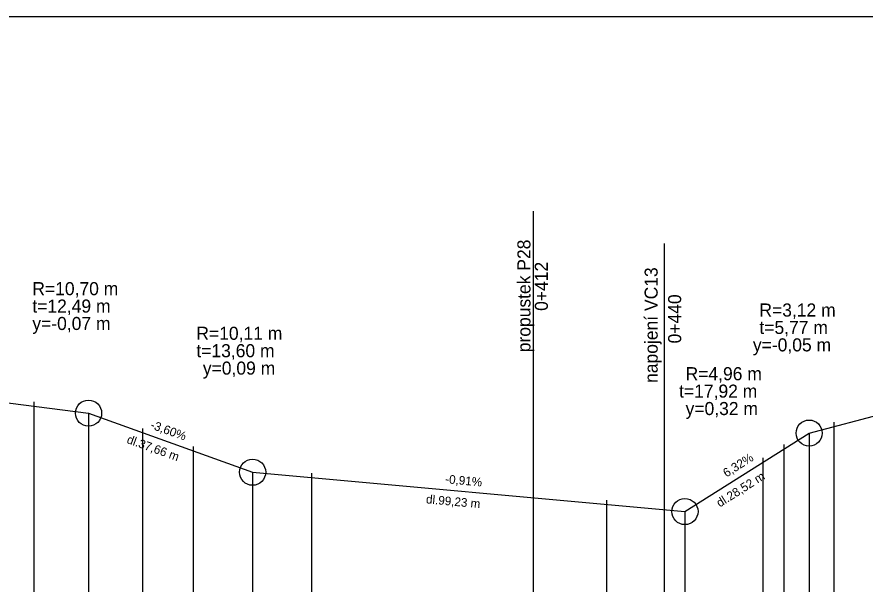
# Model space of a CAD drawing. Extents: x -632716 to -629545, y -1094726 to -1088285.
# Drawn here: x -632192 to -631997.4, y -1090800.4 to -1090670.2 of the extents above; entities that cross this region are included whole.
import ezdxf

# ---------------------------------------------------------------- set-up
doc = ezdxf.new("R2010")
doc.units = 0
for name, color, linetype in [('formát', 7, 'Continuous'), ('SKLONY_NIVELETA', 7, 'Continuous'), ('SKLONY_POPIS', 7, 'Continuous'), ('TECNY_NIVELETA', 7, 'Continuous')]:
    doc.layers.add(name, color=color, linetype=linetype)

msp = doc.modelspace()

# ---------------------------------------------------------------- linework, layer by layer
at = {"layer": 'formát'}
msp.add_lwpolyline([(-632585.29, -1091264.2), (-630730.3, -1091264.2), (-630730.3, -1090670.2), (-632585.29, -1090670.2)], close=True, dxfattribs=at)
at = {"layer": 'SKLONY_NIVELETA'}
for p, q in [((-632043.46, -1090722.19), (-632043.46, -1090881.59)), ((-632326.48, -1090742.03), (-632175.62, -1090761.17)), ((-632010.21, -1090765.75), (-631939.34, -1090747.15)), ((-632175.62, -1090761.17), (-632175.62, -1091015.2)), ((-632175.62, -1090761.17), (-632137.96, -1090774.73)), ((-632038.72, -1090783.77), (-632010.21, -1090765.75)), ((-632010.21, -1090765.75), (-632010.21, -1091015.2)), ((-632137.96, -1090774.73), (-632137.96, -1091015.2)), ((-632137.96, -1090774.73), (-632038.72, -1090783.77)), ((-632038.72, -1090783.77), (-632038.72, -1091015.2))]:
    msp.add_line(p, q, dxfattribs=at)
for centre in [(-632175.62, -1090761.17), (-632010.21, -1090765.75), (-632137.96, -1090774.73), (-632038.72, -1090783.77)]:
    msp.add_circle(centre, 3, dxfattribs=at)
at = {"layer": 'TECNY_NIVELETA'}
for p, q in [((-632073.46, -1090880.61), (-632073.46, -1090714.82)), ((-632188.1, -1090859.58), (-632188.1, -1090758.58)), ((-632175.62, -1090761.17), (-632175.62, -1090761.17)), ((-632004.44, -1090864.23), (-632004.44, -1090763.23)), ((-632163.13, -1090865.67), (-632163.13, -1090764.67)), ((-632010.21, -1090765.75), (-632010.21, -1090765.75)), ((-632015.98, -1090869.39), (-632015.98, -1090768.39)), ((-632151.56, -1090869.83), (-632151.56, -1090768.83)), ((-632020.8, -1090872.44), (-632020.8, -1090771.44)), ((-632137.96, -1090774.73), (-632137.96, -1090774.73)), ((-632124.36, -1090875.97), (-632124.36, -1090774.97)), ((-632056.65, -1090882.14), (-632056.65, -1090781.14)), ((-632038.72, -1090783.77), (-632038.72, -1090783.77))]:
    msp.add_line(p, q, dxfattribs=at)

# ---------------------------------------------------------------- texts
at = {"layer": 'SKLONY_POPIS'}
for s, height, rotation, p in [('propustek P28', 3, 90, (-632074.18, -1090747.19)), ('0+412', 3, 90, (-632070.18, -1090737.69)), ('napojení VC13', 3, 90, (-632044.98, -1090754.23)), ('0+440', 3, 90, (-632039.58, -1090745.16)), ('-3,60%', 2, 340.1922, (-632161.58, -1090764.63)), ('dl.37,66 m', 2, 340.1922, (-632167, -1090767.99)), ('6,32%', 2, 32.2944, (-632029.19, -1090775.97)), ('-0,91%', 2, 354.7952, (-632093.81, -1090777.25)), ('dl.28,52 m', 2, 32.2944, (-632030.71, -1090782.85)), ('dl.99,23 m', 2, 354.7952, (-632098.22, -1090781.87))]:
    msp.add_text(s, height=height, rotation=rotation, dxfattribs=at).set_placement(p)
for s, p in [('R=10,70 m', (-632188.52, -1090734.08)), ('t=12,49 m', (-632188.52, -1090738.08)), ('R=3,12 m', (-632021.63, -1090738.99)), ('y=-0,07 m', (-632188.52, -1090742.08)), ('t=5,77 m', (-632021.63, -1090742.99)), ('R=10,11 m', (-632150.87, -1090744.33)), ('y=-0,05 m', (-632023.12, -1090746.99)), ('t=13,60 m', (-632150.87, -1090748.33)), ('y=0,09 m', (-632149.38, -1090752.33)), ('R=4,96 m', (-632038.57, -1090753.61)), ('t=17,92 m', (-632040.06, -1090757.61)), ('y=0,32 m', (-632038.57, -1090761.61))]:
    msp.add_text(s, height=3, dxfattribs=at).set_placement(p)

doc.saveas('drawing.dxf')
